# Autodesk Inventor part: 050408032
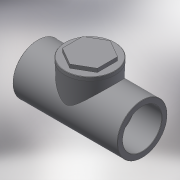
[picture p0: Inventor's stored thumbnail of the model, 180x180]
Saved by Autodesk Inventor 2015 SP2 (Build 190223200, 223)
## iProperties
Created: 2017-10
Part Number: 050408032
Material: Generic
Description: PLASSON CHECK VALVE T-CLAPPERALVE-CEMENT 32
Document SubType Name: Modeling
Designer: KIM
Density: 1 g/cm^3
Appearance: Default
Author: KIM
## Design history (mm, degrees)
derived "050408.ipt"
feature "Solid1::050408.ipt"
feature "Solid2::050408.ipt"
tag "TaggingFeature1"
body "Solid1"
other parameters: "d0" = 86, "d1" = 41, "d2" = 22, "d4" = 32, "d5" = 27.2619, "d7" = 0.30291, "d8" = 22, "d15" = 0, "d18" = 30.291, "d24" = 0.30291, "d37" = 28.7, "d38" = 3, "d39" = 0, "d41" = 41, "d42" = 3, "d43" = 38.95, "G_" = 30.291, "E_" = 41, "H_" = 86, "lt_" = 13, "l_" = 22, "d_" = 32
